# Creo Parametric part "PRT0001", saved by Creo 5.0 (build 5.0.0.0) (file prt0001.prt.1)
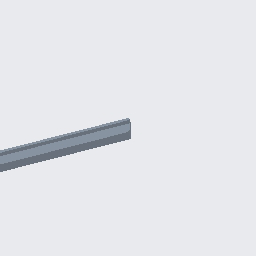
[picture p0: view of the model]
Units: Inch lbm Second (Pro/E Default); INCH, POUND, SECS

Created from: INLBS_PART_SOLID.PRT

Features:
  1. datum plane "RIGHT"
  2. datum plane "TOP"
  3. datum plane "FRONT"
  4. coordinate system
  5. sketch "Sketch 1"
  6. extrusion "Extrude 1"

Surfaces: 10 plane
